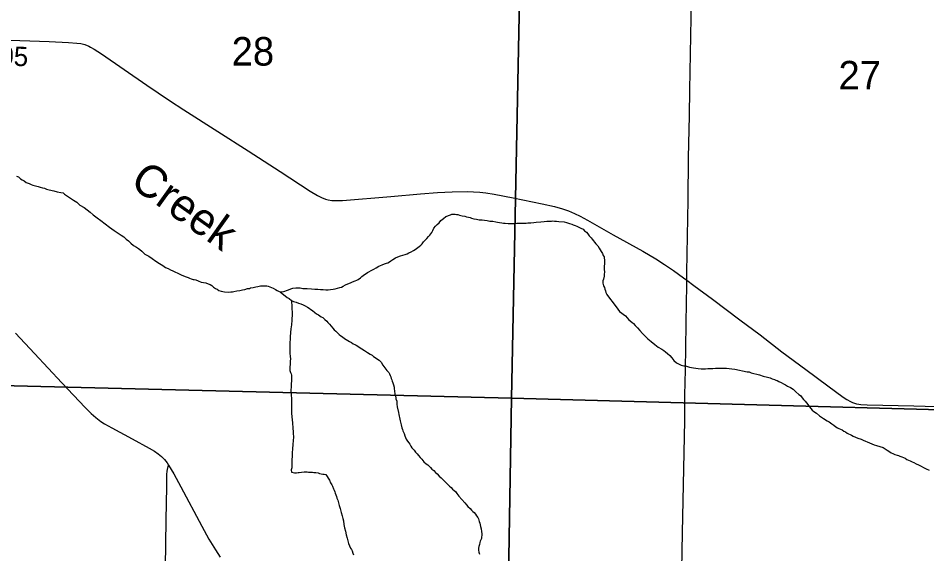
# Model space of a CAD drawing. Extents: x 1587405 to 1714697, y 1028970 to 1155083.
# Drawn here: x 1662922 to 1669958, y 1096169 to 1100319 of the extents above; entities that cross this region are included whole.
import ezdxf

# ---------------------------------------------------------------- set-up
doc = ezdxf.new("R2010")
doc.units = 0
for name, color, linetype in [('GM_X_Minor_River', 7, 'Continuous'), ('GM_X_Minor_River_Text', 7, 'Continuous'), ('GM_X_Section', 7, 'Continuous'), ('GM_X_Section_Text', 7, 'Continuous'), ('GM_X_State_Route', 7, 'Continuous'), ('GM_X_Township_Road', 7, 'Continuous'), ('GM_X_Township_Road_Text', 7, 'Continuous')]:
    doc.layers.add(name, color=color, linetype=linetype)

msp = doc.modelspace()

# ---------------------------------------------------------------- linework, layer by layer
at = {"layer": 'GM_X_Minor_River'}
for points in [[(1662907.9, 1099094.7), (1662923.9, 1099088.4), (1662939.8, 1099074.2)], [(1662939.8, 1099074.2), (1662951.8, 1099066), (1662967.8, 1099057.7), (1662983.8, 1099045.5), (1663007.9, 1099039.1), (1663021.9, 1099030.9), (1663035.9, 1099024.7), (1663076, 1099014.1), (1663092.1, 1099009.9), (1663110.2, 1099005.6), (1663124.2, 1099001.4), (1663140.2, 1098995.2), (1663162.3, 1098988.9), (1663196.5, 1098980.4), (1663222.6, 1098974), (1663252.7, 1098967.6), (1663268.8, 1098965.4), (1663280.7, 1098955.2), (1663302.7, 1098940.8), (1663326.7, 1098924.4), (1663350.7, 1098910.1), (1663374.6, 1098893.7), (1663398.5, 1098871.3), (1663432.5, 1098850.8), (1663456.5, 1098834.4), (1663478.4, 1098816), (1663502.3, 1098795.6), (1663532.2, 1098773.1), (1663562.2, 1098750.6), (1663594.1, 1098726.1), (1663628, 1098699.5), (1663665.9, 1098674.9), (1663695.9, 1098654.4), (1663717.8, 1098638.1), (1663739.9, 1098625.7), (1663757.7, 1098607.4), (1663775.7, 1098593.1), (1663793.6, 1098574.8), (1663815.5, 1098558.4), (1663837.5, 1098544.1), (1663853.5, 1098533.8), (1663863.5, 1098525.7), (1663879.4, 1098513.4), (1663901.3, 1098491), (1663933.3, 1098474.5), (1663959.3, 1098456.1), (1663987.2, 1098435.6), (1664015.2, 1098417.2), (1664041.2, 1098402.8), (1664061.1, 1098388.5), (1664083.2, 1098380.1), (1664101.2, 1098369.9), (1664119.2, 1098361.6), (1664173.3, 1098336.8), (1664183.3, 1098330.6), (1664201.3, 1098322.3), (1664221.3, 1098314.1), (1664237.4, 1098309.8), (1664247.4, 1098305.7), (1664261.4, 1098299.5), (1664275.5, 1098295.3), (1664285.5, 1098293.1), (1664297.6, 1098290.9), (1664315.6, 1098284.7), (1664339.7, 1098274.3), (1664373.8, 1098267.8), (1664393.9, 1098259.6), (1664407.9, 1098255.3), (1664419.9, 1098247.1), (1664433.8, 1098234.9), (1664449.8, 1098224.7), (1664461.8, 1098218.5), (1664475.8, 1098210.3), (1664493.9, 1098204), (1664520, 1098199.6), (1664550.2, 1098197.2), (1664568.3, 1098199), (1664580.4, 1098198.8), (1664592.5, 1098200.7), (1664614.8, 1098206.4), (1664639, 1098210.1), (1664659.2, 1098213.9), (1664677.3, 1098217.7), (1664697.5, 1098223.4), (1664711.7, 1098225.2), (1664721.8, 1098229.1), (1664740, 1098232.9), (1664762.2, 1098236.6), (1664778.3, 1098240.4), (1664798.5, 1098244.2), (1664818.7, 1098245.9), (1664832.8, 1098245.8), (1664846.9, 1098245.6), (1664856.9, 1098243.4), (1664870.9, 1098237.2), (1664895, 1098226.9), (1664913, 1098216.6), (1664927, 1098208.4), (1664937, 1098204.2), (1664951, 1098198), (1664961.1, 1098197.9)], [(1664961.1, 1098197.9), (1664977.3, 1098201.7), (1664987.3, 1098203.6), (1664999.5, 1098209.4), (1665013.7, 1098215.3), (1665031.9, 1098223.1), (1665048.1, 1098226.9), (1665070.3, 1098230.6), (1665090.4, 1098230.3), (1665104.5, 1098230.1), (1665126.6, 1098225.8), (1665158.8, 1098223.4), (1665193, 1098220.9), (1665219.2, 1098220.6), (1665241.3, 1098218.3), (1665263.5, 1098218), (1665283.6, 1098215.8), (1665303.7, 1098215.5), (1665321.8, 1098215.2), (1665340, 1098217), (1665360.2, 1098218.8), (1665376.3, 1098222.6), (1665394.5, 1098228.4), (1665412.7, 1098232.1), (1665424.8, 1098236), (1665437, 1098241.9), (1665457.3, 1098253.6), (1665475.5, 1098261.4), (1665493.7, 1098269.2), (1665509.9, 1098275.1), (1665530.2, 1098282.8), (1665544.3, 1098288.7), (1665554.5, 1098294.6), (1665572.8, 1098306.4), (1665582.9, 1098316.3), (1665593.1, 1098324.2), (1665603.3, 1098334.1), (1665615.5, 1098342), (1665625.6, 1098347.9), (1665666.2, 1098369.4), (1665676.3, 1098375.3), (1665692.6, 1098385.2), (1665714.9, 1098396.9), (1665739.2, 1098406.7), (1665759.4, 1098414.4), (1665773.6, 1098420.3), (1665783.7, 1098424.1), (1665795.9, 1098432), (1665808.1, 1098439.9), (1665822.3, 1098449.8), (1665842.6, 1098461.6), (1665860.8, 1098469.3), (1665881.1, 1098477.1), (1665899.3, 1098482.9), (1665917.5, 1098488.7), (1665933.6, 1098492.5), (1665947.8, 1098500.3), (1665964, 1098508.2), (1665982.3, 1098518), (1665996.5, 1098525.8), (1666006.6, 1098533.7), (1666027, 1098549.5), (1666039.2, 1098561.4), (1666049.4, 1098571.3), (1666059.7, 1098585.3), (1666073.9, 1098599.2), (1666086.2, 1098611.1), (1666098.5, 1098627), (1666108.7, 1098636.9), (1666116.8, 1098646.8), (1666125, 1098658.8), (1666131.3, 1098672.7), (1666139.5, 1098690.7), (1666153.8, 1098706.6), (1666166.1, 1098720.5), (1666180.4, 1098734.4), (1666194.7, 1098752.3), (1666204.9, 1098760.2), (1666215, 1098766.1), (1666233.3, 1098781.9), (1666269.8, 1098795.5), (1666279.9, 1098799.4), (1666292, 1098799.2), (1666304.1, 1098801.1), (1666316.1, 1098798.9), (1666326.2, 1098796.7), (1666340.2, 1098792.6), (1666360.3, 1098788.3), (1666380.4, 1098784), (1666394.4, 1098779.8), (1666408.5, 1098777.6), (1666420.6, 1098773.4), (1666432.6, 1098769.2), (1666450.6, 1098763), (1666470.7, 1098760.7), (1666490.8, 1098756.4), (1666515, 1098756.1), (1666533.1, 1098753.9), (1666553.2, 1098751.6), (1666573.3, 1098747.3), (1666597.4, 1098745)], [(1666597.4, 1098745), (1666619.6, 1098740.7), (1666633.6, 1098738.5), (1666647.7, 1098736.3), (1666665.8, 1098734), (1666679.9, 1098731.8), (1666691.9, 1098731.7), (1666716.1, 1098729.4), (1666740.3, 1098729), (1666760.4, 1098728.8), (1666782.6, 1098730.5), (1666804.7, 1098730.2), (1666824.9, 1098729.9), (1666841, 1098729.7), (1666855.1, 1098731.6), (1666869.2, 1098733.4), (1666891.4, 1098733.1), (1666913.5, 1098734.8), (1666933.7, 1098738.6), (1666968, 1098740.1), (1666994.2, 1098743.8), (1667016.4, 1098745.5), (1667034.6, 1098747.3), (1667050.7, 1098747.1), (1667062.8, 1098748.9), (1667074.8, 1098746.8), (1667088.9, 1098746.6), (1667109, 1098744.3), (1667149.3, 1098739.8), (1667167.3, 1098735.5), (1667189.4, 1098729.2), (1667207.5, 1098722.9), (1667219.5, 1098718.7), (1667233.5, 1098712.5), (1667247.5, 1098706.3), (1667263.6, 1098700.1), (1667277.6, 1098691.9), (1667295.6, 1098683.6), (1667307.5, 1098671.4), (1667321.5, 1098661.1), (1667333.4, 1098646.9), (1667343.3, 1098632.7), (1667357.2, 1098616.5), (1667367.1, 1098606.3), (1667377, 1098594.1), (1667385, 1098584), (1667394.9, 1098571.8), (1667408.8, 1098555.5), (1667420.6, 1098537.3), (1667436.4, 1098511), (1667446.3, 1098494.8), (1667452.2, 1098480.6), (1667458.1, 1098470.5), (1667459.9, 1098458.4), (1667461.8, 1098446.3), (1667461.6, 1098434.3), (1667461.4, 1098418.2), (1667459.1, 1098396.2), (1667458.8, 1098372.1), (1667460.6, 1098353.9), (1667460.4, 1098333.9), (1667458.2, 1098319.8), (1667453.9, 1098297.8), (1667449.7, 1098283.8), (1667449.4, 1098265.7), (1667455.2, 1098245.5), (1667461.1, 1098231.4), (1667465, 1098219.3), (1667468.8, 1098205.2), (1667472.7, 1098193.1), (1667480.6, 1098178.9), (1667508.3, 1098140.4), (1667520.2, 1098124.1), (1667534, 1098105.9), (1667551.9, 1098083.6), (1667577.6, 1098045.1), (1667623.5, 1098012.3), (1667651.3, 1097981.8), (1667673.2, 1097963.4), (1667687.2, 1097953.2), (1667699.1, 1097939), (1667717, 1097920.7), (1667734.9, 1097900.3), (1667754.7, 1097876), (1667776.6, 1097855.6), (1667798.5, 1097835.2), (1667822.4, 1097814.8), (1667852.3, 1097790.3), (1667878.3, 1097769.9), (1667906.3, 1097753.4), (1667922.3, 1097745.2), (1667934.2, 1097735), (1667950.2, 1097720.7), (1667968.1, 1097706.4), (1667982, 1097688.2), (1667997.8, 1097667.9), (1668019.7, 1097649.5), (1668039.7, 1097637.2), (1668055.8, 1097630.9), (1668075.9, 1097626.7), (1668087.9, 1097624.5)], [(1664951, 1098198), (1665004.9, 1098155.1), (1665010.9, 1098153), (1665020.9, 1098146.9), (1665036.8, 1098132.6), (1665052.8, 1098124.3), (1665074.9, 1098118), (1665092.9, 1098111.8), (1665111, 1098105.5), (1665129, 1098099.2), (1665145, 1098091), (1665161, 1098080.7), (1665175, 1098072.5), (1665189, 1098062.3), (1665201, 1098054.1), (1665218.9, 1098039.8), (1665232.9, 1098027.6), (1665246.9, 1098019.3), (1665256.9, 1098013.2), (1665268.8, 1098005), (1665280.8, 1097998.8), (1665296.8, 1097984.5), (1665310.7, 1097970.3), (1665320.6, 1097960.1), (1665332.6, 1097947.9), (1665344.5, 1097933.7), (1665358.4, 1097917.4), (1665368.3, 1097905.2), (1665380.2, 1097895.1), (1665390.2, 1097886.9), (1665408.1, 1097868.6), (1665420.1, 1097858.4), (1665434.1, 1097850.1), (1665448, 1097837.9), (1665462, 1097829.7), (1665474, 1097821.5), (1665486, 1097813.3), (1665502, 1097805.1), (1665516, 1097796.8), (1665528, 1097790.6), (1665540, 1097784.5), (1665582, 1097757.8), (1665603.9, 1097743.4), (1665625.9, 1097729.1), (1665645.9, 1097716.8), (1665661.9, 1097708.5), (1665673.9, 1097698.3), (1665685.8, 1097690.1), (1665703.8, 1097677.8), (1665717.8, 1097669.6), (1665731.7, 1097653.4), (1665745.5, 1097631.1), (1665753.5, 1097620.9), (1665761.4, 1097610.8), (1665769.3, 1097600.6), (1665777.2, 1097588.5), (1665791.1, 1097574.2), (1665797, 1097564.1), (1665802.9, 1097550), (1665806.8, 1097539.9), (1665808.7, 1097527.8), (1665814.6, 1097517.7), (1665818.5, 1097507.6), (1665822.3, 1097493.5), (1665828.2, 1097479.3), (1665832, 1097461.2), (1665833.8, 1097447.1), (1665835.7, 1097431), (1665839.4, 1097406.9), (1665843.2, 1097390.7), (1665845.1, 1097378.7), (1665846.9, 1097368.6), (1665852.8, 1097352.4), (1665852.7, 1097342.4), (1665854.5, 1097328.3), (1665856.3, 1097308.2), (1665865.8, 1097263.9), (1665869.6, 1097247.8), (1665871.5, 1097235.7), (1665873.3, 1097225.6), (1665877.2, 1097213.5), (1665879.1, 1097199.4), (1665883, 1097189.3), (1665884.8, 1097179.3), (1665886.7, 1097167.2), (1665892.5, 1097145), (1665898.4, 1097132.9), (1665900.2, 1097122.8), (1665910, 1097100.6), (1665915.9, 1097082.4), (1665925.6, 1097058.2), (1665937.5, 1097041.9), (1665945.4, 1097029.8), (1665953.3, 1097017.6), (1665961.2, 1097003.5), (1665971.1, 1096991.3), (1665987, 1096971), (1665998.9, 1096956.8), (1666010.8, 1096944.6), (1666022.7, 1096930.3), (1666034.6, 1096916.1)], [(1665036.8, 1098132.6), (1665043.5, 1098028), (1665040.9, 1097979.9), (1665038.5, 1097943.7), (1665034.2, 1097927.7), (1665034, 1097911.6), (1665029.6, 1097883.6), (1665027.2, 1097851.4), (1665024.4, 1097787.2), (1665024, 1097759.1), (1665025.6, 1097722.9), (1665027.3, 1097696.8), (1665029.1, 1097678.7), (1665028.8, 1097660.6), (1665028.6, 1097638.5), (1665026.2, 1097614.4), (1665026.1, 1097600.3), (1665025.9, 1097590.3), (1665029.8, 1097574.2), (1665035.7, 1097564.1), (1665037.6, 1097552), (1665037.4, 1097539.9), (1665037.3, 1097529.9), (1665039, 1097509.8), (1665036.7, 1097485.7), (1665034.4, 1097463.6), (1665032.1, 1097437.5), (1665033.9, 1097423.4), (1665035.7, 1097407.4), (1665039.2, 1097361.1), (1665038.3, 1097288.8), (1665037.9, 1097258.7), (1665039.5, 1097230.5), (1665045, 1097184.2), (1665048.5, 1097142), (1665050.2, 1097113.8), (1665051.9, 1097095.8), (1665053.8, 1097081.7), (1665053.6, 1097071.6), (1665051.3, 1097047.5), (1665048.9, 1097015.4), (1665046.5, 1096981.3), (1665044.1, 1096951.2), (1665043.8, 1096931.1), (1665043.7, 1096917.1), (1665041.5, 1096905), (1665041.4, 1096895), (1665041.1, 1096872.9), (1665040.6, 1096834.7), (1665036.4, 1096820.7), (1665038.2, 1096802.6), (1665050.2, 1096798.4), (1665060.3, 1096796.3), (1665076.4, 1096796.1), (1665088.5, 1096797.9), (1665098.6, 1096799.8), (1665116.7, 1096801.6), (1665134.9, 1096803.3), (1665147, 1096803.2), (1665159, 1096803), (1665169.1, 1096802.9), (1665189.2, 1096802.6), (1665201.3, 1096800.5), (1665211.4, 1096800.3), (1665225.5, 1096800.2), (1665243.5, 1096795.9), (1665255.6, 1096791.7), (1665267.6, 1096789.6), (1665281.7, 1096787.4), (1665291.7, 1096785.2), (1665303.8, 1096783.1), (1665331.4, 1096738.5), (1665341.3, 1096718.3), (1665349.1, 1096704.1), (1665355, 1096692), (1665362.8, 1096671.8), (1665368.7, 1096661.7), (1665372.6, 1096649.6), (1665376.5, 1096639.5), (1665382.4, 1096625.3), (1665386.3, 1096613.2), (1665390.1, 1096599.1), (1665396, 1096585), (1665401.8, 1096564.8), (1665407.6, 1096544.6), (1665415.3, 1096520.4), (1665423, 1096488.2), (1665430.7, 1096464), (1665436.5, 1096443.8), (1665440.3, 1096423.7), (1665444, 1096397.5), (1665449.7, 1096371.3), (1665455.4, 1096345.1), (1665461.1, 1096314.9), (1665468.8, 1096290.7), (1665474.6, 1096268.5), (1665480.4, 1096248.4), (1665486.2, 1096230.2), (1665496, 1096214), (1665501.9, 1096201.9), (1665507.8, 1096191.8)], [(1668087.9, 1097624.5), (1668104, 1097620.3), (1668120, 1097616), (1668136.1, 1097611.8), (1668150.2, 1097609.6), (1668168.3, 1097607.4), (1668186.4, 1097605.1), (1668210.5, 1097602.8), (1668230.7, 1097602.5), (1668244.7, 1097602.3), (1668260.9, 1097604.1), (1668281, 1097605.9), (1668301.2, 1097605.6), (1668321.4, 1097607.4), (1668347.5, 1097607), (1668373.7, 1097606.7), (1668389.8, 1097606.5), (1668405.9, 1097606.3), (1668426, 1097604), (1668448.2, 1097601.7), (1668470.3, 1097599.4), (1668566.7, 1097580), (1668580.8, 1097577.8), (1668596.8, 1097571.6), (1668618.9, 1097567.3), (1668641, 1097561), (1668661.1, 1097554.7), (1668691.2, 1097546.3), (1668723.3, 1097537.8), (1668745.4, 1097531.5), (1668759.4, 1097525.3), (1668777.5, 1097519), (1668789.5, 1097514.8), (1668799.5, 1097510.7), (1668811.5, 1097504.5), (1668829.5, 1097496.2), (1668847.5, 1097486), (1668863.5, 1097477.7), (1668879.5, 1097467.4), (1668901.6, 1097457.1), (1668921.5, 1097444.8), (1668943.4, 1097424.4), (1668965.3, 1097404), (1668979.3, 1097395.8), (1668993.2, 1097377.6), (1669003.1, 1097365.4), (1669015, 1097351.2), (1669024.9, 1097339), (1669036.9, 1097324.8), (1669048.7, 1097308.5), (1669060.6, 1097294.3), (1669070.6, 1097282.1), (1669082.5, 1097271.9), (1669102.5, 1097257.6), (1669126.4, 1097239.2), (1669156.3, 1097216.7), (1669186.3, 1097198.2), (1669202.4, 1097192), (1669212.3, 1097183.8), (1669222.3, 1097175.7), (1669236.3, 1097165.4), (1669252.2, 1097153.2), (1669266.2, 1097144.9), (1669276.2, 1097138.8), (1669290.3, 1097134.6), (1669302.3, 1097128.4), (1669314.3, 1097120.2), (1669328.3, 1097114), (1669340.2, 1097103.8), (1669374.3, 1097087.3), (1669388.3, 1097081.1), (1669404.3, 1097072.8), (1669424.3, 1097064.5), (1669448.4, 1097056.2), (1669464.4, 1097049.9), (1669482.5, 1097041.7), (1669496.5, 1097035.4), (1669514.5, 1097029.2), (1669532.5, 1097020.9), (1669550.6, 1097014.7), (1669568.6, 1097008.4), (1669592.7, 1097000), (1669618.8, 1096991.7), (1669634.8, 1096983.4), (1669650.8, 1096971.1), (1669670.7, 1096958.8), (1669682.7, 1096950.6), (1669694.8, 1096946.5), (1669710.8, 1096938.2), (1669726.8, 1096934), (1669738.9, 1096929.8), (1669748.9, 1096925.7), (1669762.9, 1096919.5), (1669776.9, 1096915.2), (1669789, 1096909.1), (1669803, 1096900.8), (1669829, 1096890.5), (1669845, 1096882.2), (1669857, 1096876), (1669875, 1096865.7), (1669893, 1096857.5)], [(1666034.6, 1096916.1), (1666046.5, 1096901.9), (1666062.4, 1096881.6), (1666080.3, 1096867.3), (1666094.3, 1096859.1), (1666104.3, 1096848.9), (1666114.2, 1096838.7), (1666124.1, 1096824.5), (1666140.1, 1096814.3), (1666152, 1096800.1), (1666165.9, 1096787.8), (1666181.8, 1096771.6), (1666197.8, 1096757.3), (1666211.7, 1096743), (1666223.6, 1096732.8), (1666233.6, 1096720.6), (1666247.5, 1096706.4), (1666261.4, 1096694.2), (1666273.4, 1096684), (1666285.3, 1096669.7), (1666297.2, 1096659.5), (1666307.2, 1096651.4), (1666317.1, 1096637.2), (1666333, 1096616.9), (1666380.6, 1096564), (1666392.5, 1096549.8), (1666404.4, 1096535.6), (1666420.4, 1096519.3), (1666432.3, 1096507.1), (1666442.2, 1096496.9), (1666452.2, 1096488.8), (1666462.1, 1096476.6), (1666470, 1096464.4), (1666479.9, 1096450.2), (1666485.8, 1096440.1), (1666489.7, 1096430), (1666491.6, 1096419.9), (1666497.5, 1096405.8), (1666501.2, 1096381.6), (1666507, 1096361.5), (1666508.8, 1096341.4), (1666512.6, 1096323.2), (1666512.4, 1096313.2), (1666510.2, 1096299.1), (1666508.1, 1096287.1), (1666503.9, 1096277.1), (1666499.8, 1096267.1), (1666497.6, 1096257.1), (1666493.4, 1096241.1), (1666489.2, 1096225.1), (1666487, 1096213.1), (1666486.8, 1096197), (1666488.6, 1096180.9), (1666492.5, 1096166.8)], [(1669893, 1096857.5), (1669913.1, 1096847.2), (1669933.1, 1096838.9), (1669953.1, 1096828.6), (1669975.1, 1096818.2)], [(1665507.8, 1096191.8), (1665513.7, 1096173.6), (1665517.5, 1096161.5)]]:
    msp.add_lwpolyline(points, dxfattribs=at)
at = {"layer": 'GM_X_Section'}
for points in [[(1661485.6, 1102806.5), (1666847.1, 1102659.7), (1666741, 1097373.7), (1661429.4, 1097506)], [(1666847.1, 1102659.7), (1672144.7, 1102517.4), (1672060.5, 1097231.1), (1666741, 1097373.7)], [(1666741, 1097373.7), (1666653.8, 1092126.1), (1666555.8, 1092129.2), (1661358.4, 1092269.9), (1661429.4, 1097506)], [(1672060.5, 1097231.1), (1671935.5, 1091998.3), (1666653.8, 1092126.1), (1666741, 1097373.7)]]:
    msp.add_lwpolyline(points, close=True, dxfattribs=at)
at = {"layer": 'GM_X_State_Route'}
msp.add_lwpolyline([(1662901.1, 1097877.5), (1663047, 1097721.8), (1663260.4, 1097494.2), (1663439.5, 1097302.1), (1663486, 1097256.1), (1663522.9, 1097224), (1663561.9, 1097194.6), (1663589.1, 1097176.7), (1663645.8, 1097144.2), (1663804.8, 1097058.7), (1663935.2, 1096988.8), (1663977.8, 1096963.4), (1664005, 1096944.3), (1664030.6, 1096923.2), (1664053.8, 1096899.4), (1664074.6, 1096873.5), (1664086.4, 1096856), (1664126.5, 1096789), (1664181.8, 1096688.1), (1664343, 1096383.4), (1664398.6, 1096282.9), (1664449.4, 1096198.8), (1664485.5, 1096144.2)], dxfattribs=at)
at = {"layer": 'GM_X_Township_Road'}
for points in [[(1668098.4, 1098288.5), (1668098.6, 1098350.8), (1668110.3, 1098908.9), (1668113.4, 1099237.3), (1668120, 1099565.5), (1668122.4, 1099762.6), (1668132.5, 1100320.7), (1668137.9, 1100566.9), (1668144.2, 1100911.6), (1668153.5, 1101354.8), (1668161, 1101781.6), (1668166.4, 1102077.1), (1668168.5, 1102274.1), (1668173.9, 1102388.7), (1668176, 1102470.9), (1668176.1, 1102569.6), (1668173.5, 1102611.2), (1668171.3, 1102629.8)], [(1662785.5, 1100151.6), (1663162.7, 1100137.4), (1663310.3, 1100131.3), (1663375.3, 1100126.4), (1663407.2, 1100121.7), (1663438.4, 1100113.8), (1663468.4, 1100102), (1663482.8, 1100094.8), (1663511.2, 1100078.7), (1663566.1, 1100043.2), (1663917.5, 1099801.1), (1664093.8, 1099680.8), (1664204.2, 1099609.6), (1664466.5, 1099441.2), (1664702.2, 1099291.8), (1664950.7, 1099132.2), (1665183.8, 1098978.9), (1665239.8, 1098943.8), (1665269.3, 1098928.5), (1665300.4, 1098916.5), (1665323.1, 1098911.1), (1665349.2, 1098906.9), (1665382.4, 1098905.1), (1665432.1, 1098907.1), (1665808.4, 1098938.5), (1666037.3, 1098958.7), (1666168.1, 1098968.7), (1666282.7, 1098973.5), (1666397.4, 1098975.2), (1666446.4, 1098973.9), (1666495.2, 1098970.5), (1666543.9, 1098964.9), (1666608.6, 1098954.6), (1666753.7, 1098927.6), (1666978.7, 1098881.5), (1667074.3, 1098858.6), (1667137.2, 1098840.8), (1667183.5, 1098825.1), (1667228.6, 1098806.3), (1667272.7, 1098785), (1667330.3, 1098753.9), (1667530, 1098640.3), (1667759.4, 1098512.6), (1667858.2, 1098454.4), (1667927.4, 1098410.6), (1667994.8, 1098364.1), (1668074.4, 1098306.4), (1668098.4, 1098288.5)], [(1668038.4, 1094667.9), (1668038.7, 1094695.3), (1668041.6, 1094936.4), (1668051.6, 1095527.3), (1668058.1, 1095904.9), (1668066.6, 1096331.7), (1668082.7, 1097201.7), (1668084.7, 1097398.8), (1668088.6, 1097595.7), (1668095.9, 1098121), (1668098.9, 1098235.9), (1668098.4, 1098288.5)], [(1668098.4, 1098288.5), (1668153.6, 1098247.8), (1668299.2, 1098141.2), (1668508.4, 1097982.6), (1668665.9, 1097864.4), (1668835.2, 1097734.6), (1669019.8, 1097597.8), (1669190.2, 1097469.5), (1669309.2, 1097381.6), (1669337.1, 1097363.7), (1669366.6, 1097348.1), (1669382, 1097341.7), (1669397.8, 1097336.1), (1669413.9, 1097331.8), (1669430.3, 1097328.4), (1669446.8, 1097326.1), (1669496.3, 1097322.7), (1669857.4, 1097315.4), (1670464.2, 1097296.9)], [(1664008.6, 1092205.3), (1664016.7, 1093093.1), (1664020.7, 1093306.7), (1664024.5, 1093536.8), (1664028.2, 1093750.4), (1664031.3, 1093947.6), (1664034.5, 1094095.2), (1664040.8, 1094587.6), (1664045.3, 1094867.9), (1664049.8, 1095125.1), (1664052.4, 1095411.9), (1664058.7, 1095822.1), (1664062.3, 1096065.6), (1664066.7, 1096430.6), (1664072.1, 1096691.6), (1664072.1, 1096784.7), (1664074.9, 1096808.7), (1664076.7, 1096823.4), (1664086.4, 1096856)]]:
    msp.add_lwpolyline(points, dxfattribs=at)

# ---------------------------------------------------------------- texts
at = {"layer": 'GM_X_Minor_River_Text'}
msp.add_text('Creek', height=250, rotation=324.54134, dxfattribs=at).set_placement((1663776.1, 1099025))
at = {"layer": 'GM_X_Section_Text'}
for s, p in [('28', (1664574.7, 1099951.6)), ('27', (1669273.9, 1099766.8))]:
    msp.add_text(s, height=221, rotation=0.00001, dxfattribs=at).set_placement(p)
at = {"layer": 'GM_X_Township_Road_Text'}
msp.add_text('T-205', height=150, rotation=357.75804, dxfattribs=at).set_placement((1662472.9, 1099965.9))

doc.saveas('drawing.dxf')
